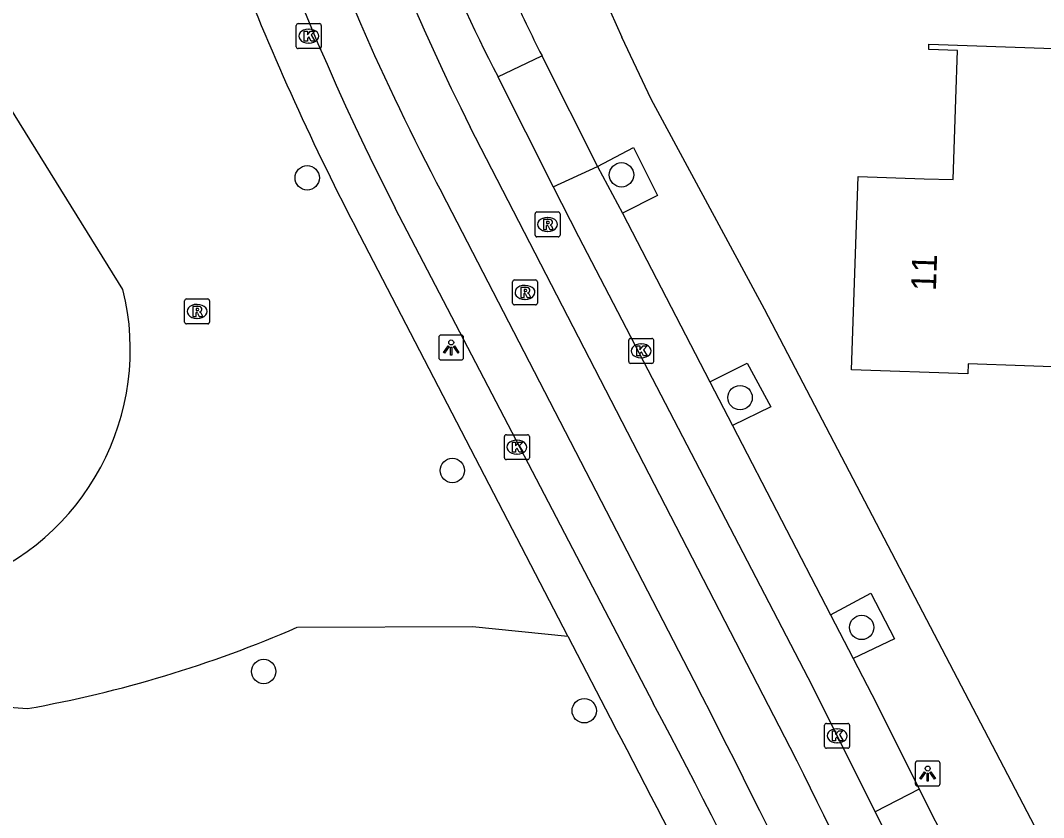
# Model space of a CAD drawing. Extents: x 161355 to 162026, y 386504 to 387459.
# Drawn here: x 161746.37 to 161787.45, y 387221.17 to 387253.16 of the extents above; entities that cross this region are included whole.
import ezdxf

# ---------------------------------------------------------------- set-up
doc = ezdxf.new("R2010")
doc.units = 0
for name, color, linetype in [('IMGEO_Boom', 7, 'Continuous'), ('IMGEO_Groenvoorziening', 7, 'Continuous'), ('IMGEO_Kolk', 7, 'Continuous'), ('IMGEO_Lichtpunt', 7, 'Continuous'), ('IMGEO_Meer_plas_ven_vijver', 7, 'Continuous'), ('IMGEO_Pand', 7, 'Continuous'), ('IMGEO_Pand_nummerreeks', 7, 'Continuous'), ('IMGEO_Parkeervlak_open', 7, 'Continuous'), ('IMGEO_Rijbaan_lokaal_gesloten', 7, 'Continuous'), ('IMGEO_Rijbaan_lokaal_open', 7, 'Continuous'), ('IMGEO_Rioolput', 7, 'Continuous'), ('IMGEO_Voetpad_open', 7, 'Continuous')]:
    doc.layers.add(name, color=color, linetype=linetype)

msp = doc.modelspace()

# ---------------------------------------------------------------- linework, layer by layer
at = {"layer": 'IMGEO_Boom'}
for centre in [(161757.882, 387246.842), (161770.502, 387246.962), (161775.263, 387238.021), (161763.709, 387235.095), (161780.144, 387228.797), (161756.135, 387227.028), (161769.005, 387225.453)]:
    msp.add_circle(centre, 0.489, dxfattribs=at)
at = {"layer": 'IMGEO_Groenvoorziening'}
for points in [[(161757.486, 387228.803), (161764.521, 387228.833), (161768.347, 387228.45)], [(161722.631, 387226.841), (161740.545, 387225.991), (161746.656, 387225.539)]]:
    msp.add_lwpolyline(points, dxfattribs=at)
msp.add_arc((161737.955, 387274.007), 49.243, 280.177, 293.367, dxfattribs=at)
at = {"layer": 'IMGEO_Kolk'}
for p, q in [((161757.445, 387252.104), (161757.445, 387252.956)), ((161757.52, 387253.03), (161758.372, 387253.03)), ((161758.446, 387252.956), (161758.446, 387252.104)), ((161757.933, 387252.81), (161757.958, 387252.81)), ((161757.956, 387252.25), (161757.931, 387252.25)), ((161758.372, 387252.03), (161757.52, 387252.03)), ((161770.792, 387239.469), (161770.792, 387240.321)), ((161770.867, 387240.395), (161771.719, 387240.395)), ((161771.28, 387240.175), (161771.305, 387240.175)), ((161771.793, 387240.321), (161771.793, 387239.469)), ((161771.719, 387239.395), (161770.867, 387239.395)), ((161771.303, 387239.615), (161771.278, 387239.615)), ((161765.803, 387235.607), (161765.803, 387236.459)), ((161765.878, 387236.533), (161766.73, 387236.533)), ((161766.804, 387236.459), (161766.804, 387235.607)), ((161766.291, 387236.313), (161766.316, 387236.313)), ((161766.314, 387235.753), (161766.289, 387235.753)), ((161766.73, 387235.533), (161765.878, 387235.533)), ((161778.732, 387224.947), (161779.584, 387224.947)), ((161778.657, 387224.021), (161778.657, 387224.873)), ((161779.145, 387224.727), (161779.17, 387224.727)), ((161779.658, 387224.873), (161779.658, 387224.021)), ((161779.168, 387224.167), (161779.143, 387224.167)), ((161779.584, 387223.947), (161778.732, 387223.947))]:
    msp.add_line(p, q, dxfattribs=at)
for points in [[(161757.445, 387252.104), (161757.445, 387252.956)], [(161757.52, 387253.03), (161758.372, 387253.03)], [(161758.446, 387252.956), (161758.446, 387252.104)], [(161757.766, 387252.73), (161757.889, 387252.73), (161757.889, 387252.579), (161758.019, 387252.73), (161758.183, 387252.73), (161758.037, 387252.579), (161758.19, 387252.33), (161758.038, 387252.33), (161757.953, 387252.494), (161757.889, 387252.427), (161757.889, 387252.33), (161757.766, 387252.33), (161757.766, 387252.73)], [(161758.372, 387252.03), (161757.52, 387252.03)], [(161770.792, 387239.469), (161770.792, 387240.321)], [(161770.867, 387240.395), (161771.719, 387240.395)], [(161771.793, 387240.321), (161771.793, 387239.469)], [(161771.113, 387240.095), (161771.236, 387240.095), (161771.236, 387239.944), (161771.366, 387240.095), (161771.53, 387240.095), (161771.384, 387239.944), (161771.537, 387239.695), (161771.385, 387239.695), (161771.3, 387239.859), (161771.236, 387239.792), (161771.236, 387239.695), (161771.113, 387239.695), (161771.113, 387240.095)], [(161771.719, 387239.395), (161770.867, 387239.395)], [(161765.803, 387235.607), (161765.803, 387236.459)], [(161765.878, 387236.533), (161766.73, 387236.533)], [(161766.804, 387236.459), (161766.804, 387235.607)], [(161766.124, 387236.233), (161766.247, 387236.233), (161766.247, 387236.082), (161766.377, 387236.233), (161766.541, 387236.233), (161766.395, 387236.082), (161766.548, 387235.833), (161766.396, 387235.833), (161766.311, 387235.997), (161766.247, 387235.93), (161766.247, 387235.833), (161766.124, 387235.833), (161766.124, 387236.233)], [(161766.73, 387235.533), (161765.878, 387235.533)], [(161778.732, 387224.947), (161779.584, 387224.947)], [(161778.657, 387224.021), (161778.657, 387224.873)], [(161778.978, 387224.647), (161779.101, 387224.647), (161779.101, 387224.496), (161779.231, 387224.647), (161779.395, 387224.647), (161779.249, 387224.496), (161779.402, 387224.247), (161779.25, 387224.247), (161779.165, 387224.411), (161779.101, 387224.344), (161779.101, 387224.247), (161778.978, 387224.247), (161778.978, 387224.647)], [(161779.658, 387224.873), (161779.658, 387224.021)], [(161779.584, 387223.947), (161778.732, 387223.947)]]:
    msp.add_lwpolyline(points, dxfattribs=at)
for centre, start, end in [((161757.522, 387252.954), 91.552, 178.448), ((161757.522, 387252.954), 91.552, 178.448), ((161758.37, 387252.954), 1.552, 88.448), ((161758.37, 387252.954), 1.552, 88.448), ((161757.522, 387252.106), 181.552, 268.448), ((161757.522, 387252.106), 181.552, 268.448), ((161758.37, 387252.106), 271.552, 358.448), ((161758.37, 387252.106), 271.552, 358.448), ((161770.869, 387240.319), 91.552, 178.448), ((161770.869, 387240.319), 91.552, 178.448), ((161771.717, 387240.319), 1.552, 88.448), ((161771.717, 387240.319), 1.552, 88.448), ((161770.869, 387239.471), 181.552, 268.448), ((161770.869, 387239.471), 181.552, 268.448), ((161771.717, 387239.471), 271.552, 358.448), ((161771.717, 387239.471), 271.552, 358.448), ((161765.88, 387236.457), 91.552, 178.448), ((161765.88, 387236.457), 91.552, 178.448), ((161766.728, 387236.457), 1.552, 88.448), ((161766.728, 387236.457), 1.552, 88.448), ((161765.88, 387235.609), 181.552, 268.448), ((161765.88, 387235.609), 181.552, 268.448), ((161766.728, 387235.609), 271.552, 358.448), ((161766.728, 387235.609), 271.552, 358.448), ((161778.734, 387224.871), 91.552, 178.448), ((161778.734, 387224.871), 91.552, 178.448), ((161779.582, 387224.871), 1.552, 88.448), ((161779.582, 387224.871), 1.552, 88.448), ((161778.734, 387224.023), 181.552, 268.448), ((161778.734, 387224.023), 181.552, 268.448), ((161779.582, 387224.023), 271.552, 358.448), ((161779.582, 387224.023), 271.552, 358.448)]:
    msp.add_arc(centre, 0.0765, start, end, dxfattribs=at)
for centre, major_axis, ratio, start_param, end_param in [((161757.932, 387252.53), (-0.387, 0.002), 0.722429, 4.712389, 7.853982), ((161757.957, 387252.53), (-0.39, 0.002), 0.717154, 1.570796, 4.712389), ((161771.279, 387239.895), (-0.387, 0.002), 0.722429, 4.712389, 7.853982), ((161771.304, 387239.895), (-0.39, 0.002), 0.717154, 1.570796, 4.712389), ((161766.29, 387236.033), (-0.387, 0.002), 0.722429, 4.712389, 7.853982), ((161766.315, 387236.033), (-0.39, 0.002), 0.717154, 1.570796, 4.712389), ((161779.144, 387224.447), (-0.387, 0.002), 0.722429, 4.712389, 7.853982), ((161779.169, 387224.447), (-0.39, 0.002), 0.717154, 1.570796, 4.712389)]:
    msp.add_ellipse(centre, major_axis=major_axis, ratio=ratio, start_param=start_param, end_param=end_param, dxfattribs=at)
at = {"layer": 'IMGEO_Lichtpunt'}
for p, q in [((161763.166, 387240.436), (161763.166, 387239.629)), ((161763.166, 387240.436), (161763.166, 387239.629)), ((161764.068, 387240.531), (161763.26, 387240.531)), ((161764.068, 387240.531), (161763.26, 387240.531)), ((161764.162, 387239.629), (161764.162, 387240.436)), ((161764.162, 387239.629), (161764.162, 387240.436)), ((161763.26, 387239.535), (161764.068, 387239.535)), ((161763.26, 387239.535), (161764.068, 387239.535)), ((161782.298, 387223.336), (161782.298, 387222.529)), ((161782.298, 387223.336), (161782.298, 387222.529)), ((161783.2, 387223.431), (161782.392, 387223.431)), ((161783.2, 387223.431), (161782.392, 387223.431)), ((161783.294, 387222.529), (161783.294, 387223.336)), ((161783.294, 387222.529), (161783.294, 387223.336)), ((161782.392, 387222.435), (161783.2, 387222.435)), ((161782.392, 387222.435), (161783.2, 387222.435))]:
    msp.add_line(p, q, dxfattribs=at)
for points in [[(161763.54, 387240.1), (161763.579, 387240.072), (161763.391, 387239.81), (161763.353, 387239.837), (161763.54, 387240.1)], [(161763.642, 387240.052), (161763.689, 387240.052), (161763.689, 387239.73), (161763.642, 387239.73), (161763.642, 387240.052)], [(161763.752, 387240.072), (161763.79, 387240.099), (161763.977, 387239.837), (161763.938, 387239.809), (161763.752, 387240.072)], [(161782.672, 387223), (161782.711, 387222.972), (161782.523, 387222.71), (161782.485, 387222.737), (161782.672, 387223)], [(161782.774, 387222.952), (161782.821, 387222.952), (161782.821, 387222.63), (161782.774, 387222.63), (161782.774, 387222.952)], [(161782.884, 387222.972), (161782.922, 387222.999), (161783.109, 387222.737), (161783.07, 387222.709), (161782.884, 387222.972)]]:
    msp.add_lwpolyline(points, dxfattribs=at)
for centre in [(161763.665, 387240.234), (161782.797, 387223.134)]:
    msp.add_circle(centre, 0.0994, dxfattribs=at)
for centre, start, end in [((161763.26, 387240.436), 90, 180), ((161763.26, 387240.436), 90, 180), ((161764.068, 387240.436), 0, 90), ((161764.068, 387240.436), 0, 90), ((161763.26, 387239.629), 180, 270), ((161763.26, 387239.629), 180, 270), ((161764.068, 387239.629), 270, 0), ((161764.068, 387239.629), 270, 360), ((161782.392, 387223.336), 90, 180), ((161782.392, 387223.336), 90, 180), ((161783.2, 387223.336), 0, 90), ((161783.2, 387223.336), 0, 90), ((161782.392, 387222.529), 180, 270), ((161782.392, 387222.529), 180, 270), ((161783.2, 387222.529), 270, 0), ((161783.2, 387222.529), 270, 360)]:
    msp.add_arc(centre, 0.0946, start, end, dxfattribs=at)
at = {"layer": 'IMGEO_Meer_plas_ven_vijver'}
msp.add_lwpolyline([(161750.484, 387242.366), (161745.308, 387250.672), (161742.341, 387252.244)], dxfattribs=at)
msp.add_arc((161740.771, 387239.954), 10.008, 289.7011, 13.9465, dxfattribs=at)
at = {"layer": 'IMGEO_Pand'}
msp.add_lwpolyline([(161798.225, 387251.265), (161798.105, 387247.786), (161793.391, 387247.948), (161793.434, 387249.189), (161791.609, 387249.251), (161791.448, 387244.498), (161789.125, 387244.577), (161788.943, 387239.219), (161784.42, 387239.373), (161784.406, 387238.979), (161779.736, 387239.138), (161780.001, 387246.898), (161782.649, 387246.808), (161783.818, 387246.768), (161783.928, 387250), (161783.994, 387251.957), (161782.84, 387251.997), (161782.847, 387252.205), (161787.845, 387252.035), (161791.343, 387251.915)], dxfattribs=at)
at = {"layer": 'IMGEO_Parkeervlak_open'}
for points in [[(161769.544, 387247.3), (161770.545, 387245.417)], [(161774.052, 387238.649), (161774.957, 387236.901)], [(161778.891, 387229.309), (161779.804, 387227.546)]]:
    msp.add_lwpolyline(points, dxfattribs=at)
at = {"layer": 'IMGEO_Rijbaan_lokaal_gesloten'}
for points in [[(161765.543, 387250.9), (161767.759, 387246.475)], [(161777.278, 387223.979), (161764.431, 387248.875)], [(161767.759, 387246.475), (161768.775, 387244.492), (161777.99, 387226.79), (161780.687, 387221.393)], [(161773.422, 387226.648), (161763.283, 387246.254)], [(161771.78, 387225.745), (161761.42, 387245.63)], [(161780.687, 387221.393), (161782.004, 387218.757), (161784.858, 387212.564)]]:
    msp.add_lwpolyline(points, dxfattribs=at)
for centre, radius, start, end in [((161851.77, 387292.719), 97.726, 190.45972, 206.65628), ((161850.191, 387292.243), 98.326, 190.3403, 207.88639), ((161857.223, 387294.692), 107.635, 191.58046, 207.11765), ((161827.32, 387282.978), 69.609, 196.5132, 207.44116), ((161389.217, 387029.38), 431.889, 24.08405, 27.17794), ((161531.038, 387097.596), 272.725, 23.16973, 28.02682), ((161444.856, 387058.011), 371.551, 23.53549, 26.53144)]:
    msp.add_arc(centre, radius, start, end, dxfattribs=at)
at = {"layer": 'IMGEO_Rijbaan_lokaal_open'}
for points in [[(161765.543, 387250.9), (161767.309, 387251.732)], [(161767.309, 387251.732), (161769.544, 387247.3)], [(161767.759, 387246.475), (161769.544, 387247.3)], [(161782.459, 387222.304), (161780.687, 387221.393)], [(161782.459, 387222.304), (161783.747, 387219.732), (161786.672, 387213.423)]]:
    msp.add_lwpolyline(points, dxfattribs=at)
at = {"layer": 'IMGEO_Rioolput'}
for p, q in [((161767.108, 387245.472), (161767.96, 387245.472)), ((161767.033, 387244.546), (161767.033, 387245.398)), ((161767.521, 387245.252), (161767.546, 387245.252)), ((161768.034, 387245.398), (161768.034, 387244.546)), ((161767.544, 387244.692), (161767.519, 387244.692)), ((161767.96, 387244.472), (161767.108, 387244.472)), ((161766.126, 387241.818), (161766.126, 387242.67)), ((161766.201, 387242.744), (161767.053, 387242.744)), ((161767.127, 387242.67), (161767.127, 387241.818)), ((161766.614, 387242.524), (161766.639, 387242.524)), ((161752.959, 387241.055), (161752.959, 387241.907)), ((161753.034, 387241.981), (161753.886, 387241.981)), ((161753.96, 387241.907), (161753.96, 387241.055)), ((161766.637, 387241.964), (161766.612, 387241.964)), ((161753.447, 387241.761), (161753.472, 387241.761)), ((161767.053, 387241.744), (161766.201, 387241.744)), ((161753.886, 387240.981), (161753.034, 387240.981)), ((161753.47, 387241.201), (161753.445, 387241.201))]:
    msp.add_line(p, q, dxfattribs=at)
for points in [[(161767.108, 387245.472), (161767.96, 387245.472)], [(161767.033, 387244.546), (161767.033, 387245.398)], [(161767.622, 387245.17), (161767.37, 387245.172), (161767.37, 387244.772)], [(161767.548, 387245.091), (161767.494, 387245.091), (161767.494, 387245.01)], [(161768.034, 387245.398), (161768.034, 387244.546)], [(161767.37, 387244.772), (161767.494, 387244.772), (161767.494, 387244.934), (161767.505, 387244.934)], [(161767.494, 387245.01), (161767.546, 387245.01)], [(161767.552, 387244.905), (161767.623, 387244.772), (161767.763, 387244.772), (161767.698, 387244.898)], [(161767.96, 387244.472), (161767.108, 387244.472)], [(161766.126, 387241.818), (161766.126, 387242.67)], [(161766.201, 387242.744), (161767.053, 387242.744)], [(161767.127, 387242.67), (161767.127, 387241.818)], [(161766.715, 387242.442), (161766.463, 387242.444), (161766.463, 387242.044)], [(161766.463, 387242.044), (161766.587, 387242.044), (161766.587, 387242.206), (161766.598, 387242.206)], [(161766.641, 387242.363), (161766.587, 387242.363), (161766.587, 387242.282)], [(161766.587, 387242.282), (161766.639, 387242.282)], [(161752.959, 387241.055), (161752.959, 387241.907)], [(161753.034, 387241.981), (161753.886, 387241.981)], [(161753.96, 387241.907), (161753.96, 387241.055)], [(161766.645, 387242.177), (161766.716, 387242.044), (161766.856, 387242.044), (161766.791, 387242.17)], [(161753.548, 387241.679), (161753.296, 387241.681), (161753.296, 387241.281)], [(161753.296, 387241.281), (161753.42, 387241.281), (161753.42, 387241.443), (161753.431, 387241.443)], [(161753.474, 387241.6), (161753.42, 387241.6), (161753.42, 387241.519)], [(161753.42, 387241.519), (161753.472, 387241.519)], [(161753.478, 387241.414), (161753.549, 387241.281), (161753.689, 387241.281), (161753.624, 387241.407)], [(161767.053, 387241.744), (161766.201, 387241.744)], [(161753.886, 387240.981), (161753.034, 387240.981)]]:
    msp.add_lwpolyline(points, dxfattribs=at)
for centre, radius, start, end in [((161767.11, 387245.396), 0.0765, 91.552, 178.448), ((161767.11, 387245.396), 0.0765, 91.552, 178.448), ((161767.958, 387245.396), 0.0765, 1.552, 88.448), ((161767.958, 387245.396), 0.0765, 1.552, 88.448), ((161767.554, 387244.995), 0.0964, 77.0061, 93.1865), ((161767.568, 387245.052), 0.0378, 276.6634, 79.6772), ((161767.621, 387245.06), 0.109, 350.3612, 89.416), ((161767.504, 387244.881), 0.0533, 26.0293, 88.6989), ((161767.53, 387245.199), 0.19, 274.7715, 282.9687), ((161767.619, 387245.06), 0.112, 277.5842, 350.9817), ((161767.603, 387244.845), 0.108, 29.5134, 73.7905), ((161767.11, 387244.548), 0.0765, 181.552, 268.448), ((161767.11, 387244.548), 0.0765, 181.552, 268.448), ((161767.958, 387244.548), 0.0765, 271.552, 358.448), ((161767.958, 387244.548), 0.0765, 271.552, 358.448), ((161766.203, 387242.668), 0.0765, 91.552, 178.448), ((161766.203, 387242.668), 0.0765, 91.552, 178.448), ((161767.051, 387242.668), 0.0765, 1.552, 88.448), ((161767.051, 387242.668), 0.0765, 1.552, 88.448), ((161766.597, 387242.153), 0.0533, 26.0293, 88.6989), ((161766.623, 387242.471), 0.19, 274.7715, 282.9687), ((161766.647, 387242.267), 0.0964, 77.0061, 93.1865), ((161766.661, 387242.324), 0.0378, 276.6634, 79.6772), ((161766.714, 387242.332), 0.109, 350.3612, 89.416), ((161766.712, 387242.332), 0.112, 277.5842, 350.9817), ((161766.696, 387242.117), 0.108, 29.5134, 73.7905), ((161753.036, 387241.905), 0.0765, 91.552, 178.448), ((161753.036, 387241.905), 0.0765, 91.552, 178.448), ((161753.884, 387241.905), 0.0765, 1.552, 88.448), ((161753.884, 387241.905), 0.0765, 1.552, 88.448), ((161766.203, 387241.82), 0.0765, 181.552, 268.448), ((161766.203, 387241.82), 0.0765, 181.552, 268.448), ((161767.051, 387241.82), 0.0765, 271.552, 358.448), ((161767.051, 387241.82), 0.0765, 271.552, 358.448), ((161753.43, 387241.39), 0.0533, 26.0293, 88.6989), ((161753.456, 387241.708), 0.19, 274.7715, 282.9687), ((161753.48, 387241.504), 0.0964, 77.0061, 93.1865), ((161753.494, 387241.561), 0.0378, 276.6634, 79.6772), ((161753.547, 387241.569), 0.109, 350.3612, 89.416), ((161753.545, 387241.569), 0.112, 277.5842, 350.9817), ((161753.529, 387241.354), 0.108, 29.5134, 73.7905), ((161753.036, 387241.057), 0.0765, 181.552, 268.448), ((161753.036, 387241.057), 0.0765, 181.552, 268.448), ((161753.884, 387241.057), 0.0765, 271.552, 358.448), ((161753.884, 387241.057), 0.0765, 271.552, 358.448)]:
    msp.add_arc(centre, radius, start, end, dxfattribs=at)
for centre, major_axis, ratio, start_param, end_param in [((161767.52, 387244.972), (-0.387, 0.002), 0.722429, 4.712389, 7.853982), ((161767.545, 387244.972), (-0.39, 0.002), 0.717154, 1.570796, 4.712389), ((161766.613, 387242.244), (-0.387, 0.002), 0.722429, 4.712389, 7.853982), ((161766.638, 387242.244), (-0.39, 0.002), 0.717154, 1.570796, 4.712389), ((161753.446, 387241.481), (-0.387, 0.002), 0.722429, 4.712389, 7.853982), ((161753.471, 387241.481), (-0.39, 0.002), 0.717154, 1.570796, 4.712389)]:
    msp.add_ellipse(centre, major_axis=major_axis, ratio=ratio, start_param=start_param, end_param=end_param, dxfattribs=at)
at = {"layer": 'IMGEO_Voetpad_open'}
for points in [[(161787.096, 387220.809), (161776.242, 387241.569), (161771.687, 387250), (161770.52, 387252.481)], [(161769.544, 387247.3), (161770.988, 387248.065), (161771.942, 387246.131), (161770.545, 387245.417)], [(161770.545, 387245.417), (161774.052, 387238.649)], [(161768.347, 387228.45), (161759.805, 387244.896)], [(161774.052, 387238.649), (161775.548, 387239.402), (161776.503, 387237.657), (161774.957, 387236.901)], [(161774.957, 387236.901), (161778.891, 387229.309)], [(161778.891, 387229.309), (161780.507, 387230.178), (161781.457, 387228.346), (161779.804, 387227.546)], [(161768.347, 387228.45), (161770.238, 387224.808)], [(161779.804, 387227.546), (161780.739, 387225.741), (161782.459, 387222.304)]]:
    msp.add_lwpolyline(points, dxfattribs=at)
for centre, radius, start, end in [((161842.074, 387285.79), 78.927, 191.96619, 204.96253), ((161856.272, 387294.883), 108.649, 201.13235, 207.39184), ((161830.959, 387283.824), 71.282, 204.43728, 206.75739), ((161551.292, 387108.419), 247.96, 24.1133, 27.99451)]:
    msp.add_arc(centre, radius, start, end, dxfattribs=at)

# ---------------------------------------------------------------- texts
at = {"layer": 'IMGEO_Pand_nummerreeks'}
msp.add_text('11', height=1, rotation=88.0464, dxfattribs=at).set_placement((161783.125, 387242.285))

doc.saveas('drawing.dxf')
